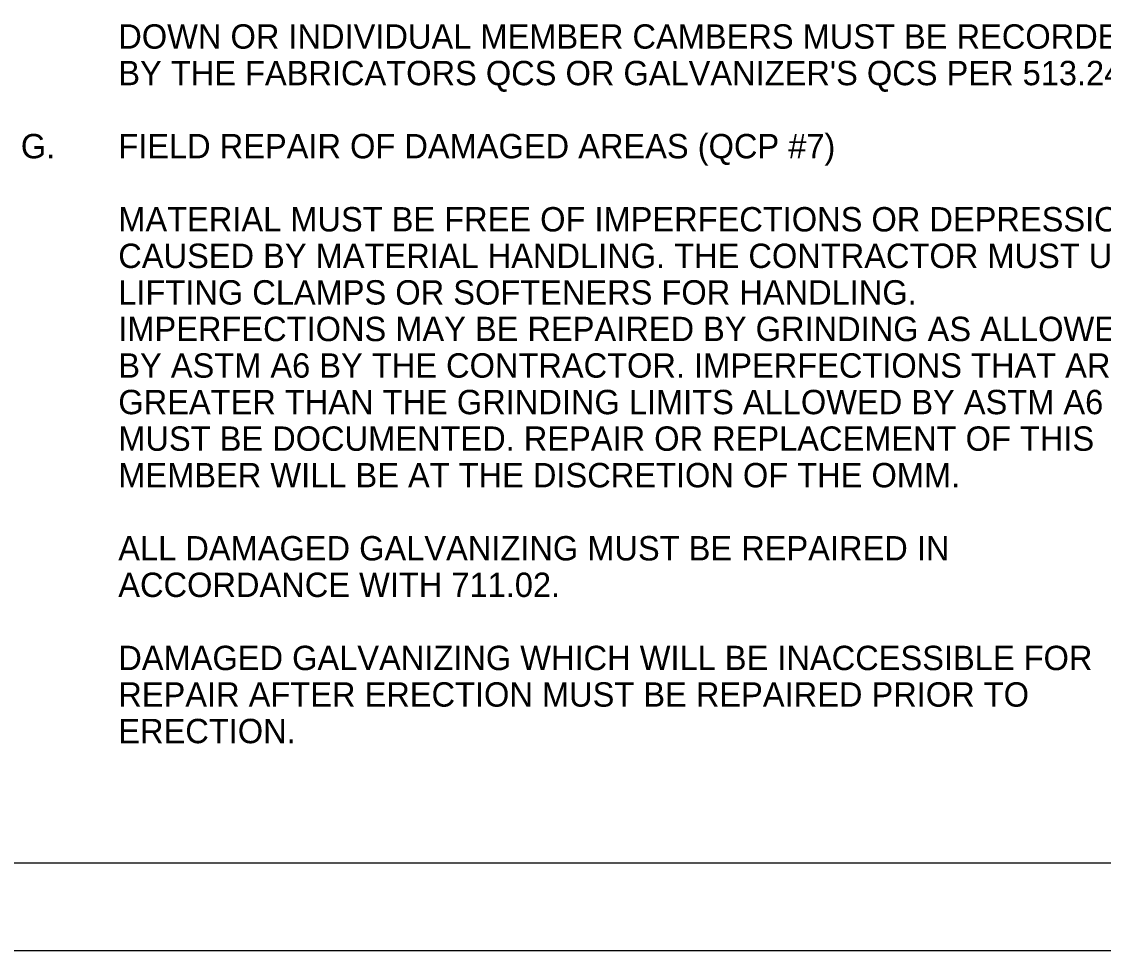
# Model space of a CAD drawing. Extents: x 0 to 45.3, y 0 to 22.
# Drawn here: x 24.66 to 30.88, y 0 to 5.34 of the extents above; entities that cross this region are included whole.
import ezdxf

# ---------------------------------------------------------------- set-up
doc = ezdxf.new("R2010")
doc.units = 0
for name, color, linetype in [('BR_P_Gen_Text', 7, 'Continuous'), ('SH_Border', 7, 'Continuous'), ('SH_Cut_Line', 7, 'Continuous')]:
    doc.layers.add(name, color=color, linetype=linetype)

msp = doc.modelspace()

# ---------------------------------------------------------------- linework, layer by layer
at = {"layer": 'SH_Border'}
msp.add_lwpolyline([(1.5, 21.5), (33.5, 21.5), (33.5, 0.5), (1.5, 0.5)], close=True, dxfattribs=at)
at = {"layer": 'SH_Cut_Line'}
msp.add_lwpolyline([(0, 0), (34, 0), (34, 22), (0, 22)], close=True, dxfattribs=at)

# ---------------------------------------------------------------- texts
at = {"layer": 'BR_P_Gen_Text'}
for s, p in [('DOWN OR INDIVIDUAL MEMBER CAMBERS MUST BE RECORDED ', (25.22, 5.18)), ("BY THE FABRICATORS QCS OR GALVANIZER'S QCS PER 513.24.", (25.22, 4.97)), ('G. ', (24.66, 4.55)), ('FIELD REPAIR OF DAMAGED AREAS (QCP #7)', (25.22, 4.55)), ('MATERIAL MUST BE FREE OF IMPERFECTIONS OR DEPRESSIONS ', (25.22, 4.13)), ('CAUSED BY MATERIAL HANDLING. THE CONTRACTOR MUST USE ', (25.22, 3.92)), ('LIFTING CLAMPS OR SOFTENERS FOR HANDLING. ', (25.22, 3.71)), ('IMPERFECTIONS MAY BE REPAIRED BY GRINDING AS ALLOWED ', (25.22, 3.5)), ('BY ASTM A6 BY THE CONTRACTOR. IMPERFECTIONS THAT ARE ', (25.22, 3.29)), ('GREATER THAN THE GRINDING LIMITS ALLOWED BY ASTM A6 ', (25.22, 3.08)), ('MUST BE DOCUMENTED. REPAIR OR REPLACEMENT OF THIS ', (25.22, 2.87)), ('MEMBER WILL BE AT THE DISCRETION OF THE OMM.', (25.22, 2.66)), ('ALL DAMAGED GALVANIZING MUST BE REPAIRED IN ', (25.22, 2.24)), ('ACCORDANCE WITH 711.02.', (25.22, 2.03)), ('DAMAGED GALVANIZING WHICH WILL BE INACCESSIBLE FOR ', (25.22, 1.61)), ('REPAIR AFTER ERECTION MUST BE REPAIRED PRIOR TO ', (25.22, 1.4)), ('ERECTION.', (25.22, 1.19))]:
    msp.add_text(s, height=0.14, dxfattribs=at).set_placement(p)

doc.saveas('drawing.dxf')
